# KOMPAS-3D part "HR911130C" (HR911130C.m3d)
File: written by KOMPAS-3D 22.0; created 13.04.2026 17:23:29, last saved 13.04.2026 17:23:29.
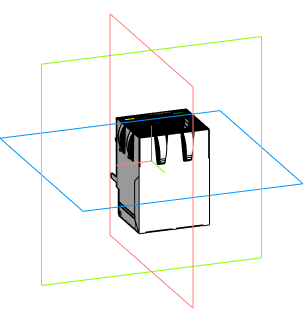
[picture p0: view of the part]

Document properties: Автор: Andrey; Полное имя файла: C:\Users\User1\Documents\HR911130C.m3d

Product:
- Part/product: HR911130C

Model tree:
1. Операция без истории:1
2. Операция без истории:2
3. Операция без истории:3
4. Операция без истории:4
5. Операция без истории:5
6. Операция без истории:6
7. Операция без истории:7
8. Операция без истории:8
9. Операция без истории:9
10. Операция без истории:10
11. Операция без истории:11
12. Операция без истории:12
13. Операция без истории:13
14. Операция без истории:14
15. Операция без истории:15
16. Операция без истории:16
17. Операция без истории:17
18. Операция без истории:18
19. Операция без истории:19
20. Операция без истории:20
21. Операция без истории:21
22. Операция без истории:22
23. Операция без истории:23
24. Операция без истории:24
25. Операция без истории:25
26. Операция без истории:26
27. Операция без истории:27
28. Операция без истории:28
29. Операция без истории:29
30. Операция без истории:30
31. Операция без истории:31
